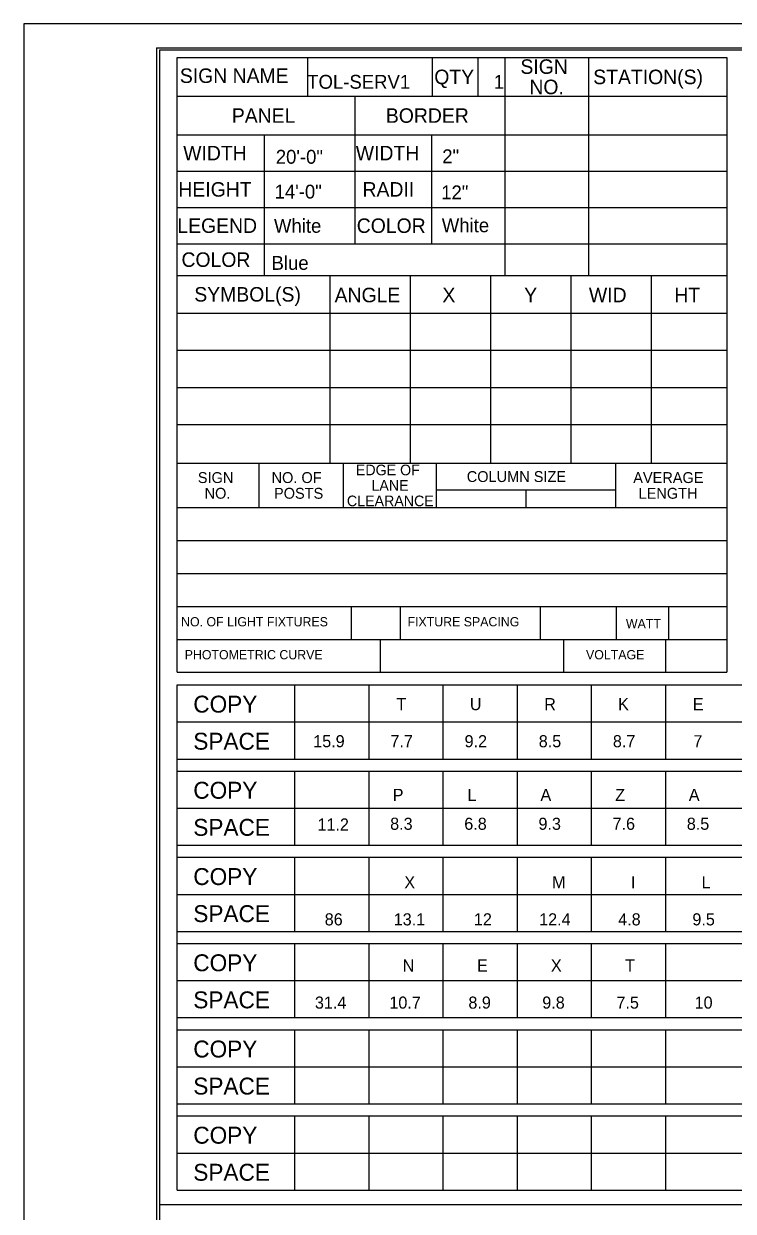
# Model space of a CAD drawing. Extents: x 17890071 to 17890754, y 17897628 to 17897992.
# Drawn here: x 17890071.13 to 17890099.93, y 17897822.34 to 17897870.5 of the extents above; entities that cross this region are included whole.
import ezdxf

# ---------------------------------------------------------------- set-up
doc = ezdxf.new("R2010")
doc.units = 0
for name, color, linetype in [('GSSign', 7, 'Continuous'), ('PlotBorder_dp', 7, 'Continuous'), ('SheetBorder_dp', 7, 'Continuous'), ('SheetLinesMisc1_dp', 7, 'Continuous'), ('SheetLinesMisc2_dp', 7, 'Continuous'), ('TextMinor', 7, 'Continuous')]:
    doc.layers.add(name, color=color, linetype=linetype)

msp = doc.modelspace()

# ---------------------------------------------------------------- linework, layer by layer
at = {"layer": 'PlotBorder_dp'}
msp.add_lwpolyline([(17890071.13, 17897766.734), (17890232.646, 17897766.734), (17890232.646, 17897870.495), (17890071.13, 17897870.495)], close=True, dxfattribs=at)
at = {"layer": 'SheetBorder_dp'}
for q in [(17890076.514, 17897767.712), (17890227.262, 17897869.516)]:
    msp.add_line((17890076.514, 17897869.516), q, dxfattribs=at)
at = {"layer": 'SheetLinesMisc1_dp'}
for p, q in [((17890082.658, 17897867.555), (17890082.658, 17897869.124)), ((17890087.705, 17897869.124), (17890087.705, 17897867.555)), ((17890089.558, 17897869.124), (17890089.558, 17897867.555)), ((17890090.662, 17897869.124), (17890090.662, 17897860.289)), ((17890094.057, 17897869.124), (17890094.057, 17897860.289)), ((17890077.364, 17897867.555), (17890099.675, 17897867.555)), ((17890084.575, 17897867.555), (17890084.575, 17897861.554)), ((17890077.364, 17897865.987), (17890099.675, 17897865.987)), ((17890080.89, 17897865.987), (17890080.89, 17897860.289)), ((17890087.686, 17897865.971), (17890087.686, 17897861.554)), ((17890077.364, 17897864.514), (17890099.675, 17897864.514)), ((17890077.364, 17897863.042), (17890099.675, 17897863.042)), ((17890077.364, 17897861.569), (17890099.675, 17897861.569)), ((17890077.364, 17897860.289), (17890099.675, 17897860.289)), ((17890083.56, 17897860.289), (17890083.56, 17897852.67)), ((17890086.82, 17897860.289), (17890086.82, 17897852.67)), ((17890090.08, 17897860.289), (17890090.08, 17897852.67)), ((17890093.34, 17897860.26), (17890093.34, 17897852.67)), ((17890096.6, 17897860.26), (17890096.6, 17897852.67)), ((17890077.369, 17897858.756), (17890099.675, 17897858.756)), ((17890077.369, 17897857.253), (17890099.675, 17897857.253)), ((17890077.369, 17897855.75), (17890099.675, 17897855.75)), ((17890077.369, 17897854.246), (17890099.675, 17897854.246)), ((17890077.364, 17897852.67), (17890099.675, 17897852.67)), ((17890080.675, 17897852.67), (17890080.675, 17897850.874)), ((17890084.097, 17897852.67), (17890084.097, 17897850.874)), ((17890087.875, 17897852.67), (17890087.875, 17897850.874)), ((17890095.151, 17897852.67), (17890095.151, 17897850.874)), ((17890087.875, 17897851.593), (17890095.146, 17897851.593)), ((17890091.511, 17897851.593), (17890091.511, 17897850.874)), ((17890077.364, 17897850.874), (17890099.675, 17897850.874)), ((17890077.364, 17897849.538), (17890099.675, 17897849.538)), ((17890077.364, 17897848.203), (17890099.675, 17897848.203)), ((17890077.364, 17897846.867), (17890099.675, 17897846.867)), ((17890077.364, 17897845.531), (17890099.675, 17897845.531))]:
    msp.add_line(p, q, dxfattribs=at)
at = {"layer": 'SheetLinesMisc2_dp'}
for p, q in [((17890076.643, 17897869.435), (17890227.099, 17897869.435)), ((17890076.643, 17897869.435), (17890076.643, 17897775.777)), ((17890077.364, 17897844.196), (17890077.364, 17897869.124)), ((17890077.364, 17897869.124), (17890099.675, 17897869.124)), ((17890099.675, 17897869.124), (17890099.675, 17897844.196)), ((17890077.364, 17897846.866), (17890099.67, 17897846.866)), ((17890084.422, 17897846.866), (17890084.422, 17897845.531)), ((17890086.415, 17897846.866), (17890086.415, 17897845.531)), ((17890092.09, 17897846.866), (17890092.09, 17897845.531)), ((17890095.177, 17897846.866), (17890095.177, 17897845.531)), ((17890097.306, 17897846.866), (17890097.306, 17897845.531)), ((17890077.364, 17897845.531), (17890099.67, 17897845.531)), ((17890085.592, 17897845.531), (17890085.592, 17897844.196)), ((17890093.035, 17897845.531), (17890093.035, 17897844.196)), ((17890097.177, 17897845.531), (17890097.177, 17897844.196)), ((17890077.364, 17897844.196), (17890099.67, 17897844.196)), ((17890077.364, 17897844.196), (17890099.675, 17897844.196)), ((17890077.364, 17897843.684), (17890151.359, 17897843.684)), ((17890077.364, 17897823.197), (17890077.364, 17897843.684)), ((17890082.127, 17897843.684), (17890082.127, 17897840.678)), ((17890085.138, 17897843.684), (17890085.138, 17897840.678)), ((17890088.148, 17897843.684), (17890088.148, 17897840.678)), ((17890091.158, 17897843.684), (17890091.158, 17897840.678)), ((17890094.168, 17897843.684), (17890094.168, 17897840.678)), ((17890097.177, 17897843.684), (17890097.177, 17897840.678)), ((17890077.364, 17897842.181), (17890151.359, 17897842.181)), ((17890077.364, 17897840.678), (17890151.359, 17897840.678)), ((17890077.364, 17897840.188), (17890151.359, 17897840.188)), ((17890082.127, 17897840.188), (17890082.127, 17897837.182)), ((17890085.138, 17897840.188), (17890085.138, 17897837.182)), ((17890088.148, 17897840.188), (17890088.148, 17897837.182)), ((17890091.158, 17897840.188), (17890091.158, 17897837.182)), ((17890094.168, 17897840.188), (17890094.168, 17897837.182)), ((17890097.177, 17897840.188), (17890097.177, 17897837.182)), ((17890077.364, 17897838.684), (17890151.359, 17897838.685)), ((17890077.364, 17897837.182), (17890151.359, 17897837.182)), ((17890077.364, 17897836.692), (17890151.359, 17897836.692)), ((17890082.127, 17897836.692), (17890082.127, 17897833.686)), ((17890085.138, 17897836.692), (17890085.138, 17897833.686)), ((17890088.148, 17897836.692), (17890088.148, 17897833.686)), ((17890091.158, 17897836.692), (17890091.158, 17897833.686)), ((17890094.168, 17897836.692), (17890094.168, 17897833.686)), ((17890097.177, 17897836.692), (17890097.177, 17897833.686)), ((17890077.364, 17897835.188), (17890151.359, 17897835.188)), ((17890077.364, 17897833.686), (17890151.359, 17897833.686)), ((17890077.364, 17897833.195), (17890151.359, 17897833.195)), ((17890082.127, 17897833.195), (17890082.127, 17897830.189)), ((17890085.138, 17897833.195), (17890085.138, 17897830.189)), ((17890088.148, 17897833.195), (17890088.148, 17897830.189)), ((17890091.158, 17897833.195), (17890091.158, 17897830.189)), ((17890094.168, 17897833.195), (17890094.168, 17897830.189)), ((17890097.177, 17897833.195), (17890097.177, 17897830.189)), ((17890077.364, 17897831.692), (17890151.359, 17897831.692)), ((17890077.364, 17897830.189), (17890151.359, 17897830.189)), ((17890077.364, 17897829.699), (17890151.359, 17897829.699)), ((17890082.127, 17897829.699), (17890082.127, 17897826.693)), ((17890085.138, 17897829.699), (17890085.138, 17897826.693)), ((17890088.148, 17897829.699), (17890088.148, 17897826.693)), ((17890091.158, 17897829.699), (17890091.158, 17897826.693)), ((17890094.168, 17897829.699), (17890094.168, 17897826.693)), ((17890097.177, 17897829.699), (17890097.177, 17897826.693)), ((17890077.364, 17897828.196), (17890151.359, 17897828.196)), ((17890077.364, 17897826.693), (17890151.359, 17897826.693)), ((17890077.364, 17897826.202), (17890151.359, 17897826.202)), ((17890082.127, 17897826.202), (17890082.127, 17897823.197)), ((17890085.138, 17897826.202), (17890085.138, 17897823.197)), ((17890088.148, 17897826.202), (17890088.148, 17897823.197)), ((17890091.158, 17897826.202), (17890091.158, 17897823.197)), ((17890094.168, 17897826.202), (17890094.168, 17897823.197)), ((17890097.177, 17897826.202), (17890097.177, 17897823.197)), ((17890077.364, 17897824.7), (17890151.359, 17897824.7)), ((17890077.364, 17897823.197), (17890151.359, 17897823.197)), ((17890076.643, 17897822.606), (17890151.871, 17897822.606))]:
    msp.add_line(p, q, dxfattribs=at)

# ---------------------------------------------------------------- texts
at = {"layer": 'GSSign'}
for s, height, p in [('TOL-SERV1', 0.5624, (17890082.637, 17897867.859)), ('1', 0.562, (17890090.21, 17897867.857)), ('20\'-0"', 0.5624, (17890081.361, 17897864.818)), ('2"', 0.5624, (17890088.118, 17897864.839)), ('14\'-0"', 0.5624, (17890081.313, 17897863.406)), ('12"', 0.5624, (17890088.075, 17897863.375)), ('White', 0.5624, (17890081.288, 17897862.019)), ('White', 0.5624, (17890088.1, 17897862.041)), ('Blue', 0.5624, (17890081.189, 17897860.515)), ('T', 0.49, (17890086.26, 17897842.658)), ('U', 0.49, (17890089.239, 17897842.658)), ('R', 0.49, (17890092.256, 17897842.658)), ('K', 0.49, (17890095.255, 17897842.658)), ('E', 0.49, (17890098.289, 17897842.658)), ('15.9', 0.4902, (17890082.881, 17897841.155)), ('7.7', 0.4902, (17890086.013, 17897841.155)), ('9.2', 0.4902, (17890089.025, 17897841.155)), ('8.5', 0.4902, (17890092.036, 17897841.155)), ('8.7', 0.4902, (17890095.044, 17897841.155)), ('7', 0.49, (17890098.311, 17897841.155)), ('P', 0.49, (17890086.108, 17897838.978)), ('L', 0.49, (17890089.142, 17897838.978)), ('A', 0.49, (17890092.105, 17897838.978)), ('Z', 0.49, (17890095.139, 17897838.978)), ('A', 0.49, (17890098.126, 17897838.978)), ('11.2', 0.4902, (17890083.054, 17897837.778)), ('8.3', 0.4902, (17890086.004, 17897837.807)), ('6.8', 0.4902, (17890089.013, 17897837.807)), ('9.3', 0.4902, (17890092.025, 17897837.807)), ('7.6', 0.4902, (17890095.032, 17897837.807)), ('8.5', 0.4902, (17890098.045, 17897837.807)), ('X', 0.49, (17890086.58, 17897835.434)), ('M', 0.49, (17890092.578, 17897835.434)), ('I', 0.49, (17890095.775, 17897835.434)), ('L', 0.49, (17890098.645, 17897835.434)), ('86', 0.4902, (17890083.348, 17897833.931)), ('13.1', 0.4902, (17890086.149, 17897833.931)), ('12', 0.4902, (17890089.404, 17897833.931)), ('12.4', 0.4902, (17890092.053, 17897833.931)), ('4.8', 0.4902, (17890095.261, 17897833.931)), ('9.5', 0.4902, (17890098.272, 17897833.931)), ('N', 0.49, (17890086.508, 17897832.058)), ('E', 0.49, (17890089.53, 17897832.058)), ('X', 0.49, (17890092.529, 17897832.058)), ('T', 0.49, (17890095.54, 17897832.058)), ('31.4', 0.4902, (17890082.95, 17897830.555)), ('10.7', 0.4902, (17890085.972, 17897830.555)), ('8.9', 0.4902, (17890089.18, 17897830.555)), ('9.8', 0.4902, (17890092.179, 17897830.555)), ('7.5', 0.4902, (17890095.189, 17897830.555)), ('10', 0.4902, (17890098.363, 17897830.555))]:
    msp.add_text(s, height=height, dxfattribs=at).set_placement(p)
at = {"layer": 'TextMinor'}
for s, height, p in [('SIGN', 0.5882, (17890091.292, 17897868.463)), ('SIGN NAME', 0.5882, (17890077.468, 17897868.094)), ('QTY', 0.5882, (17890087.796, 17897868.045)), ('STATION(S)', 0.5882, (17890094.246, 17897868.045)), ('NO.', 0.5882, (17890091.656, 17897867.639)), ('PANEL', 0.5882, (17890079.578, 17897866.477)), ('BORDER', 0.5882, (17890085.831, 17897866.477)), ('WIDTH', 0.5882, (17890077.604, 17897864.956)), ('WIDTH', 0.5882, (17890084.608, 17897864.956)), ('HEIGHT', 0.5882, (17890077.408, 17897863.484)), ('RADII', 0.5882, (17890084.883, 17897863.484)), ('LEGEND', 0.5882, (17890077.366, 17897862.012)), ('COLOR', 0.5882, (17890084.648, 17897862.012)), ('COLOR', 0.5882, (17890077.533, 17897860.635)), ('SYMBOL(S)', 0.5882, (17890078.054, 17897859.229)), ('ANGLE', 0.5882, (17890083.75, 17897859.2)), ('X', 0.588, (17890088.125, 17897859.2)), ('Y', 0.588, (17890091.445, 17897859.2)), ('WID', 0.5882, (17890094.072, 17897859.2)), ('HT', 0.5882, (17890097.538, 17897859.2)), ('EDGE OF', 0.4313, (17890084.612, 17897852.184)), ('SIGN', 0.4411, (17890078.197, 17897851.87)), ('NO. OF', 0.4411, (17890081.19, 17897851.87)), ('COLUMN SIZE', 0.44113, (17890089.113, 17897851.911)), ('AVERAGE', 0.4411, (17890095.871, 17897851.87)), ('NO.', 0.4411, (17890078.47, 17897851.233)), ('POSTS', 0.4411, (17890081.289, 17897851.233)), ('LANE', 0.4313, (17890085.245, 17897851.556)), ('LENGTH', 0.4411, (17890096.088, 17897851.233)), ('CLEARANCE', 0.4313, (17890084.249, 17897850.929)), ('NO. OF LIGHT FIXTURES', 0.37485, (17890077.518, 17897846.057)), ('FIXTURE SPACING', 0.37485, (17890086.708, 17897846.057)), ('WATT', 0.3749, (17890095.574, 17897845.982)), ('PHOTOMETRIC CURVE', 0.37485, (17890077.665, 17897844.721)), ('VOLTAGE', 0.3749, (17890093.954, 17897844.721)), ('COPY', 0.6862, (17890078.013, 17897842.56)), ('SPACE', 0.6862, (17890078.013, 17897841.056)), ('COPY', 0.6862, (17890078.013, 17897839.067)), ('SPACE', 0.6862, (17890078.013, 17897837.563)), ('COPY', 0.6862, (17890078.013, 17897835.567)), ('SPACE', 0.6862, (17890078.013, 17897834.064)), ('COPY', 0.6862, (17890078.013, 17897832.071)), ('SPACE', 0.6862, (17890078.013, 17897830.568)), ('COPY', 0.6862, (17890078.013, 17897828.574)), ('SPACE', 0.6862, (17890078.013, 17897827.071)), ('COPY', 0.6862, (17890078.013, 17897825.079)), ('SPACE', 0.6862, (17890078.013, 17897823.576))]:
    msp.add_text(s, height=height, dxfattribs=at).set_placement(p)

doc.saveas('drawing.dxf')
